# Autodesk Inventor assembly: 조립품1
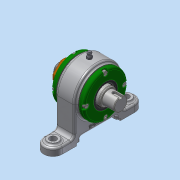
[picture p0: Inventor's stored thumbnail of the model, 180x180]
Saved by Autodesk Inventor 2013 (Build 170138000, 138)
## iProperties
Created: 2019-05
Part Number: 조립품1
Document SubType Name: Assembly
Designer: dg
Author: dg
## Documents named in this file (13)
- C:\Users\dg\Desktop\490504V1028\조립품1.iam
- C:\Users\dg\Desktop\490504V1028\본체.ipt
- C:\Users\dg\Desktop\490504V1028\개스킷.ipt
- C:\Users\dg\Desktop\490504V1028\그리스니플 M6.ipt
- 그리스니플  M6.ipt
- C:\Users\dg\Desktop\490504V1028\그리스니플개스킷.ipt
- C:\Users\dg\Desktop\490504V1028\베어링너트.ipt
- C:\Users\dg\Desktop\490504V1028\볼트 M4.ipt
- C:\Users\dg\Desktop\490504V1028\앵귤러 볼 베어링 7205.ipt
- C:\Users\dg\Desktop\490504V1028\오일 실 28 40 5 B.ipt
- C:\Users\dg\Desktop\490504V1028\축.ipt
- C:\Users\dg\Desktop\490504V1028\칼라.ipt
- C:\Users\dg\Desktop\490504V1028\커버.ipt
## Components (4 placed, 3 different names)
1. 개스킷:1
2. 그리스니플  M6:1
3. 그리스니플개스킷:1
4. 개스킷:2
